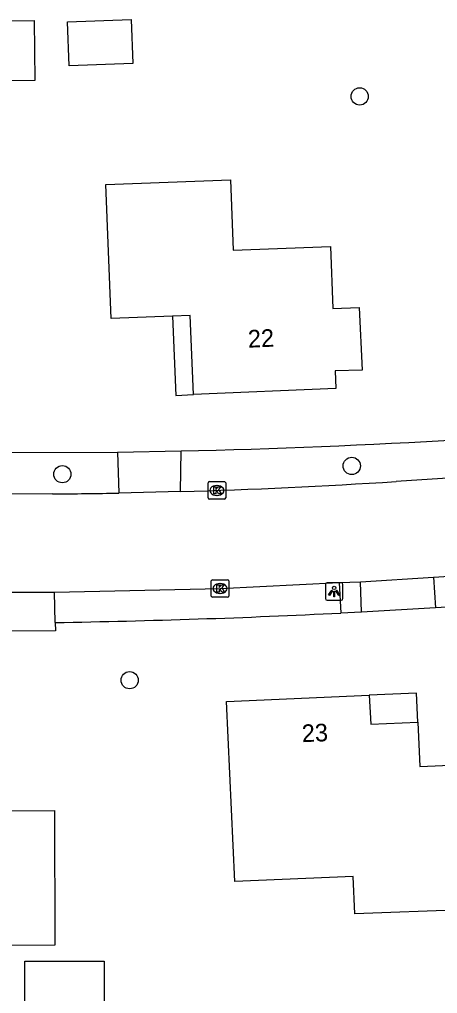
# Model space of a CAD drawing. Extents: x 162675 to 163482, y 379761 to 381227.
# Drawn here: x 163121.3 to 163145.1, y 380809.7 to 380865 of the extents above; entities that cross this region are included whole.
import ezdxf

# ---------------------------------------------------------------- set-up
doc = ezdxf.new("R2010")
doc.units = 0
for name, color, linetype in [('IMGEO_Boom', 7, 'Continuous'), ('IMGEO_Groenvoorziening', 7, 'Continuous'), ('IMGEO_Kolk', 7, 'Continuous'), ('IMGEO_Lichtpunt', 7, 'Continuous'), ('IMGEO_Pand', 7, 'Continuous'), ('IMGEO_Pand_nummerreeks', 7, 'Continuous'), ('IMGEO_Pand_overbouw', 7, 'Continuous'), ('IMGEO_Parkeervlak_halfverhard', 7, 'Continuous'), ('IMGEO_Rijbaan_lokaal_gesloten', 7, 'Continuous'), ('IMGEO_Rijbaan_lokaal_halfverhard', 7, 'Continuous'), ('IMGEO_Voetpad_open', 7, 'Continuous')]:
    doc.layers.add(name, color=color, linetype=linetype)

msp = doc.modelspace()

# ---------------------------------------------------------------- linework, layer by layer
at = {"layer": 'IMGEO_Boom'}
for centre in [(163140.675, 380860.622), (163140.224, 380839.652), (163123.783, 380839.182), (163127.605, 380827.492)]:
    msp.add_circle(centre, 0.489, dxfattribs=at)
at = {"layer": 'IMGEO_Groenvoorziening'}
msp.add_lwpolyline([(163120.437, 380840.415), (163126.923, 380840.434)], dxfattribs=at)
msp.add_arc((163120.192, 381289.265), 448.884, 271.31965, 275.389, dxfattribs=at)
at = {"layer": 'IMGEO_Kolk'}
for p, q in [((163132.061, 380837.833), (163132.061, 380838.685)), ((163132.136, 380838.759), (163132.988, 380838.759)), ((163133.062, 380838.685), (163133.062, 380837.833)), ((163132.549, 380838.539), (163132.574, 380838.539)), ((163132.988, 380837.759), (163132.136, 380837.759)), ((163132.572, 380837.979), (163132.547, 380837.979)), ((163132.245, 380832.27), (163132.245, 380833.122)), ((163132.32, 380833.196), (163133.172, 380833.196)), ((163133.246, 380833.122), (163133.246, 380832.27)), ((163132.733, 380832.976), (163132.758, 380832.976)), ((163133.172, 380832.196), (163132.32, 380832.196)), ((163132.756, 380832.416), (163132.731, 380832.416))]:
    msp.add_line(p, q, dxfattribs=at)
for points in [[(163132.061, 380837.833), (163132.061, 380838.685)], [(163132.136, 380838.759), (163132.988, 380838.759)], [(163133.062, 380838.685), (163133.062, 380837.833)], [(163132.382, 380838.459), (163132.505, 380838.459), (163132.505, 380838.308), (163132.635, 380838.459), (163132.799, 380838.459), (163132.653, 380838.308), (163132.806, 380838.059), (163132.654, 380838.059), (163132.569, 380838.223), (163132.505, 380838.156), (163132.505, 380838.059), (163132.382, 380838.059), (163132.382, 380838.459)], [(163132.988, 380837.759), (163132.136, 380837.759)], [(163132.245, 380832.27), (163132.245, 380833.122)], [(163132.32, 380833.196), (163133.172, 380833.196)], [(163133.246, 380833.122), (163133.246, 380832.27)], [(163132.566, 380832.896), (163132.689, 380832.896), (163132.689, 380832.745), (163132.819, 380832.896), (163132.983, 380832.896), (163132.837, 380832.745), (163132.99, 380832.496), (163132.838, 380832.496), (163132.753, 380832.66), (163132.689, 380832.593), (163132.689, 380832.496), (163132.566, 380832.496), (163132.566, 380832.896)], [(163133.172, 380832.196), (163132.32, 380832.196)]]:
    msp.add_lwpolyline(points, dxfattribs=at)
for centre, start, end in [((163132.138, 380838.683), 91.552, 178.448), ((163132.138, 380838.683), 91.552, 178.448), ((163132.986, 380838.683), 1.552, 88.448), ((163132.986, 380838.683), 1.552, 88.448), ((163132.138, 380837.835), 181.552, 268.448), ((163132.138, 380837.835), 181.552, 268.448), ((163132.986, 380837.835), 271.552, 358.448), ((163132.986, 380837.835), 271.552, 358.448), ((163132.322, 380833.12), 91.552, 178.448), ((163132.322, 380833.12), 91.552, 178.448), ((163133.17, 380833.12), 1.552, 88.448), ((163133.17, 380833.12), 1.552, 88.448), ((163132.322, 380832.272), 181.552, 268.448), ((163132.322, 380832.272), 181.552, 268.448), ((163133.17, 380832.272), 271.552, 358.448), ((163133.17, 380832.272), 271.552, 358.448)]:
    msp.add_arc(centre, 0.0765, start, end, dxfattribs=at)
for centre, major_axis, ratio, start_param, end_param in [((163132.548, 380838.259), (-0.387, 0.002), 0.722429, 4.712389, 7.853982), ((163132.573, 380838.259), (-0.39, 0.002), 0.717154, 1.570796, 4.712389), ((163132.732, 380832.696), (-0.387, 0.002), 0.722429, 4.712389, 7.853982), ((163132.757, 380832.696), (-0.39, 0.002), 0.717154, 1.570796, 4.712389)]:
    msp.add_ellipse(centre, major_axis=major_axis, ratio=ratio, start_param=start_param, end_param=end_param, dxfattribs=at)
at = {"layer": 'IMGEO_Lichtpunt'}
for p, q in [((163138.725, 380832.931), (163138.725, 380832.124)), ((163138.725, 380832.931), (163138.725, 380832.124)), ((163139.627, 380833.026), (163138.819, 380833.026)), ((163139.627, 380833.026), (163138.819, 380833.026)), ((163139.721, 380832.124), (163139.721, 380832.931)), ((163139.721, 380832.124), (163139.721, 380832.931)), ((163138.819, 380832.03), (163139.627, 380832.03)), ((163138.819, 380832.03), (163139.627, 380832.03))]:
    msp.add_line(p, q, dxfattribs=at)
for points in [[(163139.099, 380832.595), (163139.138, 380832.567), (163138.95, 380832.305), (163138.912, 380832.332), (163139.099, 380832.595)], [(163139.311, 380832.567), (163139.349, 380832.594), (163139.536, 380832.332), (163139.497, 380832.304), (163139.311, 380832.567)], [(163139.201, 380832.547), (163139.248, 380832.547), (163139.248, 380832.225), (163139.201, 380832.225), (163139.201, 380832.547)]]:
    msp.add_lwpolyline(points, dxfattribs=at)
msp.add_circle((163139.224, 380832.729), 0.0994, dxfattribs=at)
for centre, start, end in [((163138.819, 380832.931), 90, 180), ((163138.819, 380832.931), 90, 180), ((163139.627, 380832.931), 0, 90), ((163139.627, 380832.931), 0, 90), ((163138.819, 380832.124), 180, 270), ((163138.819, 380832.124), 180, 270), ((163139.627, 380832.124), 270, 0), ((163139.627, 380832.124), 270, 360)]:
    msp.add_arc(centre, 0.0946, start, end, dxfattribs=at)
at = {"layer": 'IMGEO_Pand'}
for points in [[(163122.217, 380861.522), (163117.647, 380861.488), (163117.621, 380864.888), (163122.191, 380864.922), (163122.217, 380861.522)], [(163127.784, 380862.491), (163124.167, 380862.352), (163124.07, 380864.85), (163127.688, 380864.989), (163127.784, 380862.491)], [(163133.342, 380855.89), (163133.496, 380851.893), (163139.012, 380852.105), (163139.147, 380848.588), (163140.646, 380848.645), (163140.817, 380845.09), (163139.285, 380845.046), (163139.327, 380844.047), (163131.23, 380843.708), (163131.042, 380848.186), (163130.034, 380848.147), (163126.55, 380848.013), (163126.257, 380855.617), (163133.342, 380855.89)], [(163146.241, 380822.696), (163146.629, 380814.46), (163146.558, 380814.458), (163140.39, 380814.225), (163140.299, 380816.346), (163133.583, 380816.059), (163133.113, 380826.286), (163141.222, 380826.64), (163141.301, 380825.003), (163143.975, 380825.101), (163144.089, 380822.593), (163146.241, 380822.696)], [(163116.322, 380825.602), (163116.351, 380824.591), (163119.805, 380824.601), (163119.815, 380820.082), (163123.331, 380820.09), (163123.347, 380812.458), (163116.227, 380812.444), (163116.22, 380816.452), (163111.691, 380816.442), (163111.682, 380820.972), (163110.166, 380820.969), (163110.159, 380824.585), (163111.722, 380824.595), (163111.693, 380825.571), (163116.322, 380825.602)], [(163126.163, 380807.83), (163121.645, 380807.83), (163121.645, 380811.548), (163126.163, 380811.548), (163126.163, 380807.83)]]:
    msp.add_lwpolyline(points, dxfattribs=at)
at = {"layer": 'IMGEO_Pand_overbouw'}
for points in [[(163131.23, 380843.708), (163131.042, 380848.186), (163130.034, 380848.147), (163130.23, 380843.654)], [(163143.975, 380825.101), (163143.901, 380826.75), (163141.222, 380826.64), (163141.301, 380825.003)]]:
    msp.add_lwpolyline(points, close=True, dxfattribs=at)
at = {"layer": 'IMGEO_Parkeervlak_halfverhard'}
msp.add_lwpolyline([(163153.325, 380832.093), (163144.977, 380831.596)], dxfattribs=at)
msp.add_arc((163115.256, 381322.737), 492.037, 270.9453, 272.83681, dxfattribs=at)
at = {"layer": 'IMGEO_Rijbaan_lokaal_gesloten'}
for points in [[(163162.556, 380840.168), (163157.127, 380839.698), (163142.738, 380838.768)], [(163130.499, 380838.193), (163127.001, 380838.11)], [(163123.218, 380838.062), (163120.377, 380838.056)], [(163144.869, 380833.344), (163153.175, 380833.877)], [(163140.718, 380833.079), (163144.869, 380833.344)], [(163123.341, 380832.497), (163132.746, 380832.696), (163139.513, 380833.027)], [(163139.513, 380833.027), (163140.718, 380833.079)], [(163119.744, 380832.482), (163123.341, 380832.497)]]:
    msp.add_lwpolyline(points, dxfattribs=at)
for centre, radius, start, end in [((163120.768, 381175.855), 337.802, 271.65068, 273.72898), ((163120.575, 381195.465), 357.413, 270.4237, 271.0302)]:
    msp.add_arc(centre, radius, start, end, dxfattribs=at)
at = {"layer": 'IMGEO_Rijbaan_lokaal_halfverhard'}
for points in [[(163144.869, 380833.344), (163144.977, 380831.596)], [(163140.779, 380831.348), (163140.718, 380833.079)], [(163144.977, 380831.596), (163140.779, 380831.348)]]:
    msp.add_lwpolyline(points, dxfattribs=at)
at = {"layer": 'IMGEO_Voetpad_open'}
for points in [[(163126.923, 380840.434), (163130.53, 380840.5)], [(163126.923, 380840.434), (163127.001, 380838.11)], [(163130.499, 380838.193), (163130.53, 380840.5)], [(163139.513, 380833.027), (163139.608, 380831.303)], [(163123.374, 380830.767), (163123.341, 380832.497)], [(163140.779, 380831.348), (163139.608, 380831.303)], [(163123.374, 380830.767), (163123.388, 380830.302), (163119.732, 380830.269), (163119.673, 380830.754)]]:
    msp.add_lwpolyline(points, dxfattribs=at)

# ---------------------------------------------------------------- texts
at = {"layer": 'IMGEO_Pand_nummerreeks'}
for s, rotation, p in [('22', 2.397, (163134.344, 380846.361)), ('23', 2.4981, (163137.408, 380823.971))]:
    msp.add_text(s, height=1, rotation=rotation, dxfattribs=at).set_placement(p)

doc.saveas('drawing.dxf')
